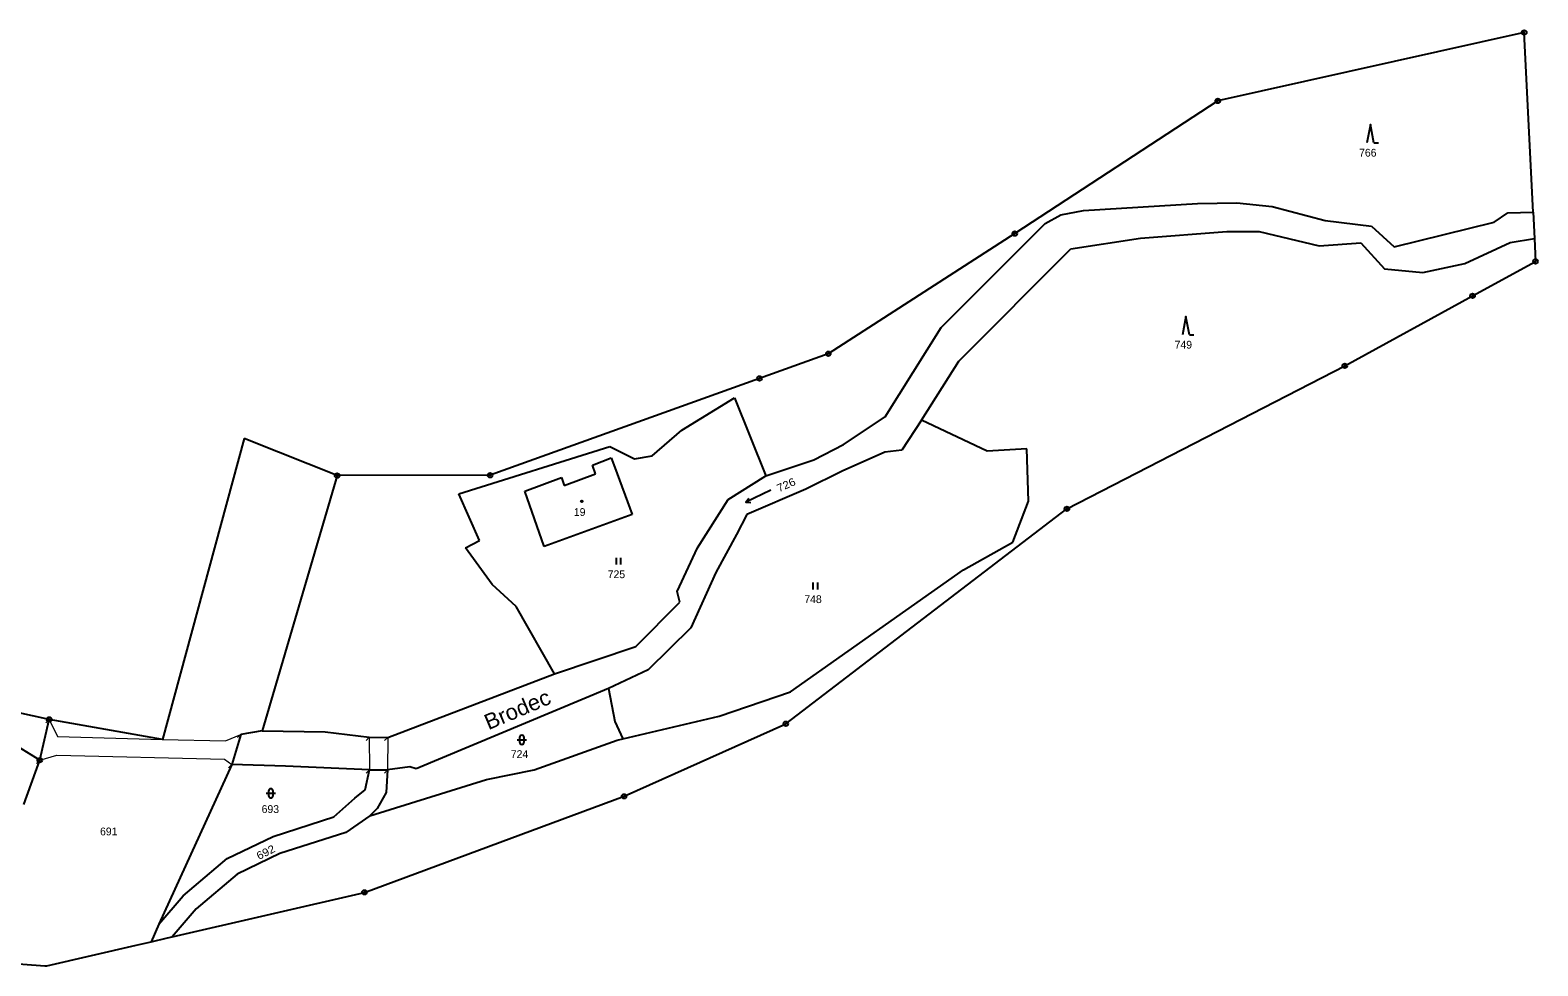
# Model space of a CAD drawing. Extents: x -719614 to -717765, y -1095834 to -1093862.
# Drawn here: x -718094 to -717765.3, y -1095215.3 to -1095011.4 of the extents above; entities that cross this region are included whole.
import ezdxf
from ezdxf.enums import TextEntityAlignment as Align

# ---------------------------------------------------------------- set-up
doc = ezdxf.new("R2010")
doc.units = 0
doc.header["$LTSCALE"] = 0.68
for name, color, linetype, lineweight in [('1', 7, 'Continuous', 25), ('3', 7, 'Continuous', 25), ('4', 7, 'Continuous', 13), ('5', 7, 'Continuous', 25), ('8', 7, 'Continuous', 25)]:
    doc.layers.add(name, color=color, linetype=linetype, lineweight=lineweight)
doc.layers.add('2', color=7, linetype='Continuous')
doc.layers.add('7', color=7, linetype='Continuous')

msp = doc.modelspace()

# ---------------------------------------------------------------- linework, layer by layer
at = {"layer": '1'}
for p, q in [((-717768.28, -1095011.88), (-717835.08, -1095026.81)), ((-717766.34, -1095051.03), (-717768.28, -1095011.88)), ((-717872.68, -1095053.52), (-717869.26, -1095051.62)), ((-717869.26, -1095051.62), (-717864.32, -1095050.66)), ((-717864.32, -1095050.66), (-717839.47, -1095049.14)), ((-717839.47, -1095049.14), (-717830.96, -1095049.03)), ((-717830.96, -1095049.03), (-717823.24, -1095049.83)), ((-717823.24, -1095049.83), (-717811.66, -1095052.86)), ((-717774.84, -1095053.26), (-717771.85, -1095051.18)), ((-717771.85, -1095051.18), (-717766.34, -1095051.03)), ((-717766.34, -1095051.03), (-717766.06, -1095056.77)), ((-717895.36, -1095076.21), (-717872.68, -1095053.52)), ((-717851.93, -1095056.75), (-717833.13, -1095055.27)), ((-717833.13, -1095055.27), (-717826.06, -1095055.29)), ((-717826.06, -1095055.29), (-717812.95, -1095058.37)), ((-717811.66, -1095052.86), (-717801.57, -1095054.09)), ((-717801.57, -1095054.09), (-717796.61, -1095058.6)), ((-717796.61, -1095058.6), (-717774.84, -1095053.26)), ((-717867.09, -1095059.04), (-717851.93, -1095056.75)), ((-717812.95, -1095058.37), (-717803.92, -1095057.77)), ((-717803.92, -1095057.77), (-717798.76, -1095063.43)), ((-717781.22, -1095062.21), (-717771.33, -1095057.67)), ((-717771.33, -1095057.67), (-717766.06, -1095056.77)), ((-717766.06, -1095056.77), (-717765.81, -1095061.79)), ((-717891.49, -1095083.53), (-717867.09, -1095059.04)), ((-717779.54, -1095069.3), (-717765.81, -1095061.79)), ((-717798.76, -1095063.43), (-717790.36, -1095064.2)), ((-717790.36, -1095064.2), (-717781.22, -1095062.21)), ((-717807.4, -1095084.54), (-717779.54, -1095069.3)), ((-717907.6, -1095095.65), (-717895.36, -1095076.21)), ((-717919.98, -1095081.92), (-717934.97, -1095087.3)), ((-717899.66, -1095096.41), (-717891.49, -1095083.53)), ((-717867.96, -1095115.71), (-717807.4, -1095084.54)), ((-717934.97, -1095087.3), (-717993.71, -1095108.4)), ((-717951.93, -1095098.58), (-717940.45, -1095091.54)), ((-717940.45, -1095091.54), (-717933.61, -1095108.53)), ((-717916.68, -1095101.67), (-717907.6, -1095095.65)), ((-717899.66, -1095096.41), (-717903.93, -1095102.96)), ((-717885.36, -1095103.17), (-717899.66, -1095096.41)), ((-718047.34, -1095100.39), (-718065.13, -1095166.03)), ((-718039.82, -1095103.39), (-718047.34, -1095100.39)), ((-717958.35, -1095104.16), (-717951.93, -1095098.58)), ((-718027.06, -1095108.48), (-718039.82, -1095103.39)), ((-718000.49, -1095112.42), (-717967.58, -1095102.16)), ((-717971.37, -1095106.18), (-717967.34, -1095104.63)), ((-717967.58, -1095102.16), (-717962.25, -1095104.83)), ((-717967.34, -1095104.63), (-717966.51, -1095106.74)), ((-717962.25, -1095104.83), (-717958.35, -1095104.16)), ((-717923.14, -1095105.07), (-717916.68, -1095101.67)), ((-717907.68, -1095103.34), (-717916.96, -1095107.54)), ((-717903.93, -1095102.96), (-717907.68, -1095103.34)), ((-717876.71, -1095102.62), (-717885.36, -1095103.17)), ((-717876.34, -1095114.04), (-717876.71, -1095102.62)), ((-717970.75, -1095108.08), (-717971.37, -1095106.18)), ((-717966.51, -1095106.74), (-717962.73, -1095116.94)), ((-717933.61, -1095108.53), (-717923.14, -1095105.07)), ((-717916.96, -1095107.54), (-717924.88, -1095111.45)), ((-718027.06, -1095108.48), (-718043.4, -1095164.08)), ((-717993.71, -1095108.4), (-718027.06, -1095108.48)), ((-717986.16, -1095111.9), (-717978.14, -1095108.92)), ((-717978.14, -1095108.92), (-717977.53, -1095110.64)), ((-717977.53, -1095110.64), (-717970.75, -1095108.08)), ((-717941.79, -1095113.7), (-717933.61, -1095108.53)), ((-717996.04, -1095122.62), (-718000.49, -1095112.42)), ((-717981.89, -1095123.93), (-717986.16, -1095111.9)), ((-717948.52, -1095124.22), (-717941.79, -1095113.7)), ((-717924.88, -1095111.45), (-717937.76, -1095116.94)), ((-717879.79, -1095122.98), (-717876.34, -1095114.04)), ((-717962.73, -1095116.94), (-717981.89, -1095123.93)), ((-717937.76, -1095116.94), (-717939.99, -1095121.33)), ((-717929.23, -1095162.57), (-717867.96, -1095115.71)), ((-717999.08, -1095124.19), (-717996.04, -1095122.62)), ((-717993.23, -1095132.19), (-717999.08, -1095124.19)), ((-717952.93, -1095133.73), (-717948.52, -1095124.22)), ((-717939.99, -1095121.33), (-717944.48, -1095129.63)), ((-717890.52, -1095129.01), (-717879.79, -1095122.98)), ((-717944.48, -1095129.63), (-717949.97, -1095141.68)), ((-717928.22, -1095155.62), (-717890.52, -1095129.01)), ((-717988.04, -1095137), (-717993.23, -1095132.19)), ((-717952.37, -1095136.03), (-717952.93, -1095133.73)), ((-717979.67, -1095151.66), (-717988.04, -1095137)), ((-717961.9, -1095145.75), (-717952.37, -1095136.03)), ((-717949.97, -1095141.68), (-717959.22, -1095150.8)), ((-717979.67, -1095151.66), (-717961.9, -1095145.75)), ((-718016.02, -1095165.53), (-717979.67, -1095151.66)), ((-717959.22, -1095150.8), (-717967.92, -1095154.89)), ((-718089.84, -1095161.63), (-718109.87, -1095157.2)), ((-717967.92, -1095154.89), (-718009.83, -1095172.38)), ((-717967.92, -1095154.89), (-717966.5, -1095162.08)), ((-717943.77, -1095160.95), (-717928.22, -1095155.62)), ((-718091.87, -1095170.5), (-718111.03, -1095158.79)), ((-718091.87, -1095170.5), (-718089.84, -1095161.63)), ((-718074.97, -1095164.28), (-718089.84, -1095161.63)), ((-717966.5, -1095162.08), (-717964.75, -1095165.83)), ((-717964.75, -1095165.83), (-717943.77, -1095160.95)), ((-718065.13, -1095166.03), (-718074.97, -1095164.28)), ((-718048.07, -1095164.89), (-718050.01, -1095171.47)), ((-718043.4, -1095164.08), (-718048.07, -1095164.89)), ((-718043.4, -1095164.08), (-718029.69, -1095164.33)), ((-718029.69, -1095164.33), (-718020.04, -1095165.51)), ((-718020.04, -1095165.51), (-718016.02, -1095165.53)), ((-717984.07, -1095172.58), (-717966.04, -1095166.13)), ((-717966.04, -1095166.13), (-717964.75, -1095165.83)), ((-718095.35, -1095180.18), (-718091.87, -1095170.5)), ((-718050.01, -1095171.47), (-718065.93, -1095206.25)), ((-718038.32, -1095171.8), (-718050.01, -1095171.47)), ((-718019.99, -1095172.64), (-718038.32, -1095171.8)), ((-718020.97, -1095176.96), (-718019.99, -1095172.64)), ((-718019.99, -1095172.64), (-718019.33, -1095172.63)), ((-718019.33, -1095172.63), (-718016.89, -1095172.62)), ((-718016.89, -1095172.62), (-718016.04, -1095172.6)), ((-718016.04, -1095172.6), (-718016.37, -1095177.57)), ((-718011.17, -1095171.98), (-718016.04, -1095172.6)), ((-718009.83, -1095172.38), (-718011.17, -1095171.98)), ((-717994.49, -1095174.7), (-717984.07, -1095172.58)), ((-718023.17, -1095178.82), (-718020.97, -1095176.96)), ((-718019.93, -1095182.64), (-717994.49, -1095174.7)), ((-718027.8, -1095182.89), (-718023.17, -1095178.82)), ((-718016.37, -1095177.57), (-718018.35, -1095181.06)), ((-718041.01, -1095187.12), (-718027.8, -1095182.89)), ((-718019.93, -1095182.64), (-718025.16, -1095186.24)), ((-718018.35, -1095181.06), (-718019.93, -1095182.64)), ((-718025.16, -1095186.24), (-718039.53, -1095190.85)), ((-718051.05, -1095191.94), (-718041.01, -1095187.12)), ((-718060.63, -1095200.1), (-718051.05, -1095191.94)), ((-718039.53, -1095190.85), (-718048.85, -1095195.32)), ((-718048.85, -1095195.32), (-718057.8, -1095202.94)), ((-718063.04, -1095209.02), (-718021.1, -1095199.32)), ((-718065.93, -1095206.25), (-718060.63, -1095200.1)), ((-718057.8, -1095202.94), (-718063.04, -1095209.02)), ((-718065.93, -1095206.25), (-718067.58, -1095210.07)), ((-718067.58, -1095210.07), (-718064.06, -1095209.26)), ((-718064.06, -1095209.26), (-718063.04, -1095209.02)), ((-718090.34, -1095215.34), (-718070.88, -1095210.84)), ((-718070.88, -1095210.84), (-718067.58, -1095210.07)), ((-718100.35, -1095214.61), (-718090.78, -1095215.31)), ((-718090.78, -1095215.31), (-718090.34, -1095215.34))]:
    msp.add_line(p, q, dxfattribs=at)
for points in [[(-717835.08, -1095026.81), (-717879.34, -1095055.72), (-717919.98, -1095081.92)], [(-718021.1, -1095199.32), (-717964.49, -1095178.39), (-717929.23, -1095162.57)]]:
    msp.add_lwpolyline(points, dxfattribs=at)
at = {"layer": '3'}
for p, q in [((-717801.07, -1095035.96), (-717800.074, -1095035.96)), ((-717841.28, -1095077.81), (-717840.284, -1095077.81)), ((-717937.936, -1095114.295), (-717937.277, -1095113.416)), ((-717966.181, -1095127.87), (-717966.181, -1095126.37)), ((-717965.18, -1095127.87), (-717965.18, -1095126.37)), ((-717923.281, -1095133.28), (-717923.281, -1095131.78)), ((-717922.28, -1095133.28), (-717922.28, -1095131.78)), ((-717987.791, -1095166.061), (-717985.789, -1095166.061)), ((-717987.291, -1095165.561), (-717987.291, -1095166.562)), ((-717986.289, -1095166.562), (-717986.289, -1095165.561)), ((-718042.511, -1095177.731), (-718040.509, -1095177.731)), ((-718042.011, -1095177.231), (-718042.011, -1095178.232)), ((-718041.009, -1095178.232), (-718041.009, -1095177.231))]:
    msp.add_line(p, q, dxfattribs=at)
for points in [[(-717801.07, -1095035.96), (-717801.82, -1095031.96), (-717802.57, -1095035.96)], [(-717841.28, -1095077.81), (-717842.03, -1095073.81), (-717842.78, -1095077.81)], [(-717932.543, -1095111.665), (-717937.936, -1095114.295), (-717936.837, -1095114.317)]]:
    msp.add_lwpolyline(points, dxfattribs=at)
for centre, start, end in [((-717986.79, -1095165.5609), 0, 180), ((-717986.79, -1095166.5609), 180, 359.98789), ((-718041.51, -1095177.2309), 0, 180), ((-718041.51, -1095178.2309), 180, 359.98789)]:
    msp.add_arc(centre, 0.5, start, end, dxfattribs=at)
at = {"layer": '4'}
for p, q in [((-718090.548, -1095162.337), (-718089.841, -1095161.63)), ((-718089.84, -1095161.63), (-718088.03, -1095165.37)), ((-718088.03, -1095165.37), (-718065.13, -1095166.03)), ((-718065.13, -1095166.03), (-718051.4, -1095166.3)), ((-718051.4, -1095166.3), (-718048.07, -1095164.89)), ((-718048.778, -1095165.597), (-718048.071, -1095164.89)), ((-718091.87, -1095170.5), (-718088.15, -1095169.45)), ((-718088.15, -1095169.45), (-718051.63, -1095170.26)), ((-718051.63, -1095170.26), (-718050.01, -1095171.47)), ((-718092.578, -1095171.207), (-718091.871, -1095170.5)), ((-718050.718, -1095172.177), (-718050.011, -1095171.47)), ((-718020.698, -1095173.347), (-718019.991, -1095172.64)), ((-718016.748, -1095173.307), (-718016.041, -1095172.6))]:
    msp.add_line(p, q, dxfattribs=at)
for points in [[(-718020.748, -1095166.217), (-718020.041, -1095165.51), (-718019.99, -1095172.64)], [(-718016.728, -1095166.237), (-718016.021, -1095165.53), (-718016.04, -1095172.6)]]:
    msp.add_lwpolyline(points, dxfattribs=at)
at = {"layer": '5'}
msp.add_circle((-717973.7168, -1095114.0992), 0.175, dxfattribs=at)
at = {"layer": '8'}
for centre, radius in [((-717768.28, -1095011.8799), 0.5), ((-717768.28, -1095011.8799), 0.0303), ((-717835.08, -1095026.8099), 0.5), ((-717835.08, -1095026.8099), 0.0303), ((-717879.34, -1095055.7199), 0.5), ((-717879.34, -1095055.7199), 0.0303), ((-717765.81, -1095061.7899), 0.5), ((-717765.81, -1095061.7899), 0.0303), ((-717779.54, -1095069.2999), 0.5), ((-717779.54, -1095069.2999), 0.0303), ((-717919.98, -1095081.9199), 0.5), ((-717919.98, -1095081.9199), 0.0303), ((-717807.4, -1095084.5399), 0.5), ((-717807.4, -1095084.5399), 0.0303), ((-717934.97, -1095087.2999), 0.5), ((-717934.97, -1095087.2999), 0.0303), ((-718027.06, -1095108.4799), 0.5), ((-717993.71, -1095108.3999), 0.5), ((-718027.06, -1095108.4799), 0.0303), ((-717993.71, -1095108.3999), 0.0303), ((-717867.96, -1095115.7099), 0.5), ((-717867.96, -1095115.7099), 0.0303), ((-718089.84, -1095161.6299), 0.5), ((-718089.84, -1095161.6299), 0.0303), ((-717929.23, -1095162.5699), 0.5), ((-717929.23, -1095162.5699), 0.0303), ((-718091.87, -1095170.4999), 0.5), ((-718091.87, -1095170.4999), 0.0303), ((-717964.49, -1095178.3899), 0.5), ((-717964.49, -1095178.3899), 0.0303), ((-718021.1, -1095199.3199), 0.5), ((-718021.1, -1095199.3199), 0.0303)]:
    msp.add_circle(centre, radius, dxfattribs=at)

# ---------------------------------------------------------------- texts
at = {"layer": '2'}
for s, p in [('766', (-717802.379, -1095038.942)), ('749', (-717842.589, -1095080.792)), ('19', (-717974.179, -1095117.272)), ('725', (-717966.169, -1095130.832)), ('748', (-717923.309, -1095136.262)), ('724', (-717987.289, -1095170.042)), ('693', (-718041.609, -1095182.022)), ('691', (-718076.829, -1095186.892))]:
    msp.add_text(s, height=1.7, dxfattribs=at).set_placement(p, align=Align.CENTER)
at = {"layer": '2', "width": 1.1}
for s, rotation, p in [('726', 24, (-717928.8217, -1095111.2726)), ('692', 27, (-718042.2209, -1095191.3325))]:
    msp.add_text(s, height=1.7, rotation=rotation, dxfattribs=at).set_placement(p, align=Align.CENTER)
at = {"layer": '7', "width": 1.05}
msp.add_text('Brodec', height=3.4, rotation=23, dxfattribs=at).set_placement((-717987.0987, -1095161.0282), align=Align.CENTER)

doc.saveas('drawing.dxf')
